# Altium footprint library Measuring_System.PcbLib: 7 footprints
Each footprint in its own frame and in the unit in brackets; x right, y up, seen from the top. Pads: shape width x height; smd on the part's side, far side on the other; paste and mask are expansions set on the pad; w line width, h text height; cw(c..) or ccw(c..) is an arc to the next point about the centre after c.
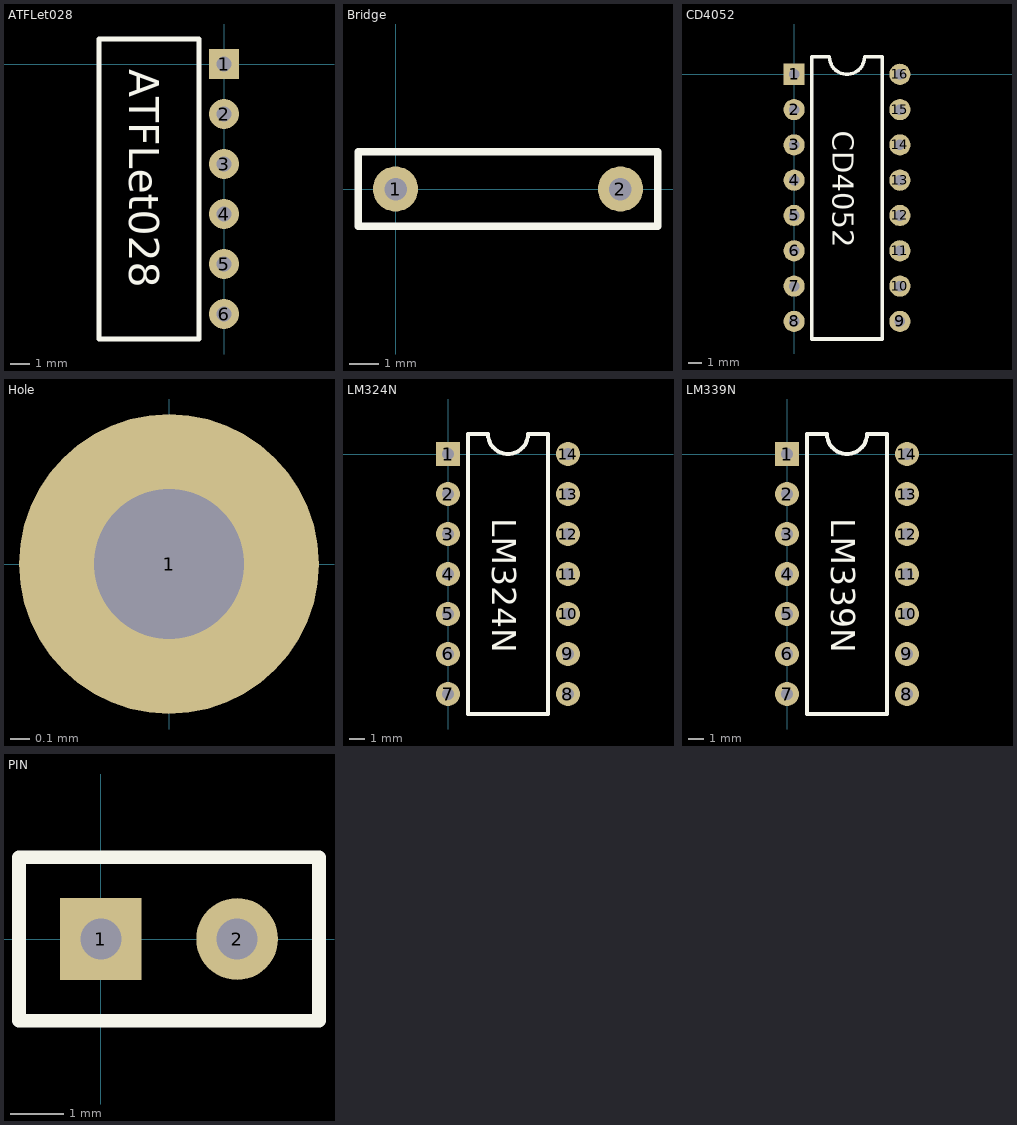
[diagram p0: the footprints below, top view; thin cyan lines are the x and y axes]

## ATFLet028 [mil]
pads (6):
  rect 60x60 hole 30: 1(0,0)
  round 60 hole 30 mask+4: 2(0,-100) 3(0,-200) 4(0,-300) 5(0,-400) 6(0,-500)
Top Overlay:
  lines w10: -250,-550 -250,50 -200,50 -50,50 -50,-550 -250,-550
  text "ATFLet028" at -190,-10 h60

## Bridge [mil]
pads (2):
  round 60 hole 30 mask+4: 1(0,0) 2(300,0)
Top Overlay:
  lines w10: -50,-50 -50,50 350,50 350,-50 -50,-50

## CD4052 [mil]
pads (16):
  rect 60x60 hole 30: 1(0,0)
  round 60 hole 30 mask+4: 2(0,-100) 3(0,-200) 4(0,-300) 5(0,-400) 6(0,-500) 7(0,-600) 8(0,-700) 9(300,-700) 10(300,-600) 11(300,-500) 12(300,-400) 13(300,-300) 14(300,-200) 15(300,-100) 16(300,0)
Top Overlay:
  lines w10: 50,-750 250,-750 250,50 200,50 cw(c150,50) 100,50 50,50 50,-750
  text "CD4052" at 110,-160 h60

## Hole [mil]
pads (1):
  round 60 hole 30 mask+4: 1(0,0)

## LM324N [mil]
pads (14):
  rect 60x60 hole 30: 1(0,0)
  round 60 hole 30 mask+4: 2(0,-100) 3(0,-200) 4(0,-300) 5(0,-400) 6(0,-500) 7(0,-600) 8(300,-600) 9(300,-500) 10(300,-400) 11(300,-300) 12(300,-200) 13(300,-100) 14(300,0)
Top Overlay:
  lines w10: 50,-650 250,-650 250,50 200,50 cw(c150,50) 100,50 50,50 50,-650
  text "LM324N" at 110,-160 h60

## LM339N [mil]
pads (14):
  rect 60x60 hole 30: 1(0,0)
  round 60 hole 30 mask+4: 2(0,-100) 3(0,-200) 4(0,-300) 5(0,-400) 6(0,-500) 7(0,-600) 8(300,-600) 9(300,-500) 10(300,-400) 11(300,-300) 12(300,-200) 13(300,-100) 14(300,0)
Top Overlay:
  lines w10: 50,-650 50,50 100,50 ccw(c150,50) 200,50 250,50 250,-650 50,-650
  text "LM339N" at 110,-160 h60

## PIN [mil]
pads (2):
  rect 60x60 hole 30 mask+4: 1(0,0)
  round 60 hole 30 mask+4: 2(100,0)
Top Overlay:
  lines w10: -60,-60 160,-60 160,60 -60,60 -60,-60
